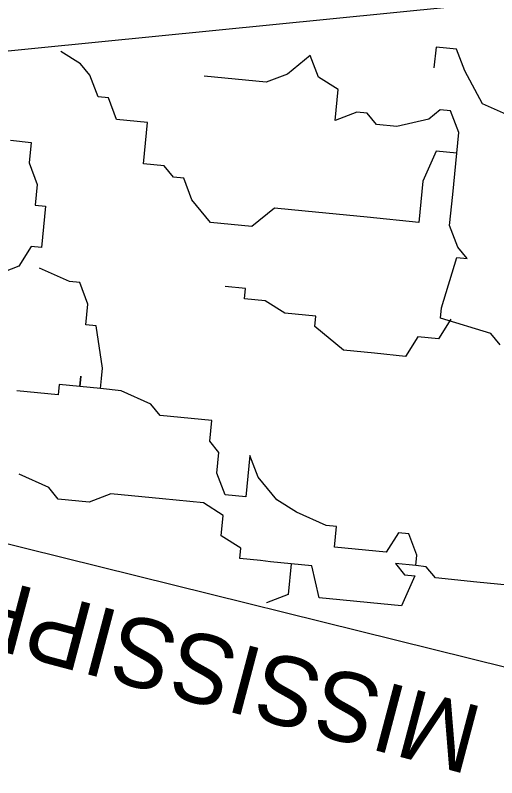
# Model space of a CAD drawing. Extents: x 1796928 to 1798191, y 245238 to 247038.
# Drawn here: x 1798053.46 to 1798065.67, y 246154.02 to 246173.35 of the extents above; entities that cross this region are included whole.
import ezdxf

# ---------------------------------------------------------------- set-up
doc = ezdxf.new("R2010")
doc.units = 0
doc.layers.add('great seal', color=7, linetype='Continuous')

msp = doc.modelspace()

# ---------------------------------------------------------------- linework, layer by layer
at = {"layer": 'great seal'}
msp.add_line((1798064.506, 246165.645), (1798064.506, 246165.645), dxfattribs=at)
msp.add_line((1798064.506, 246165.645), (1798064.506, 246165.645), dxfattribs=at)
msp.add_line((1798064.506, 246165.645), (1798064.506, 246165.645), dxfattribs=at)
msp.add_line((1798064.506, 246165.645), (1798064.506, 246165.645), dxfattribs=at)
msp.add_line((1798064.506, 246165.645), (1798064.506, 246165.645), dxfattribs=at)
msp.add_line((1798064.506, 246165.645), (1798064.506, 246165.645), dxfattribs=at)
for points in [[(1798052.498, 246172.378), (1798064.498, 246173.567)], [(1798052.498, 246172.378), (1798064.498, 246173.567)], [(1798052.498, 246172.378), (1798064.498, 246173.567)], [(1798071.46, 246166.541), (1798071.46, 246166.541), (1798070.676, 246166.619), (1798070.44, 246166.906), (1798070.179, 246166.932), (1798069.656, 246166.984), (1798069.682, 246167.245), (1798069.185, 246167.559), (1798069.001, 246168.369), (1798068.504, 246168.682), (1798068.581, 246169.467), (1798068.058, 246169.518), (1798067.064, 246170.145), (1798066.541, 246170.197), (1798066.541, 246170.197), (1798066.28, 246170.222), (1798066.305, 246170.484), (1798066.07, 246170.771), (1798065.311, 246171.11), (1798064.866, 246171.947), (1798064.656, 246172.495), (1798064.395, 246172.521), (1798064.133, 246172.547), (1798064.081, 246172.024)], [(1798071.46, 246166.541), (1798071.46, 246166.541), (1798070.676, 246166.619), (1798070.44, 246166.906), (1798070.179, 246166.932), (1798069.656, 246166.984), (1798069.682, 246167.245), (1798069.185, 246167.559), (1798069.001, 246168.369), (1798068.504, 246168.682), (1798068.581, 246169.467), (1798068.058, 246169.518), (1798067.064, 246170.145), (1798066.541, 246170.197), (1798066.541, 246170.197), (1798066.28, 246170.222), (1798066.305, 246170.484), (1798066.07, 246170.771), (1798065.311, 246171.11), (1798064.866, 246171.947), (1798064.656, 246172.495), (1798064.395, 246172.521), (1798064.133, 246172.547), (1798064.081, 246172.024)], [(1798071.46, 246166.541), (1798071.46, 246166.541), (1798070.676, 246166.619), (1798070.44, 246166.906), (1798070.179, 246166.932), (1798069.656, 246166.984), (1798069.682, 246167.245), (1798069.185, 246167.559), (1798069.001, 246168.369), (1798068.504, 246168.682), (1798068.581, 246169.467), (1798068.058, 246169.518), (1798067.064, 246170.145), (1798066.541, 246170.197), (1798066.541, 246170.197), (1798066.28, 246170.222), (1798066.305, 246170.484), (1798066.07, 246170.771), (1798065.311, 246171.11), (1798064.866, 246171.947), (1798064.656, 246172.495), (1798064.395, 246172.521), (1798064.133, 246172.547), (1798064.081, 246172.024)], [(1798064.659, 246169.855), (1798064.136, 246169.906), (1798063.797, 246169.148), (1798063.771, 246168.886), (1798063.693, 246168.102), (1798062.386, 246168.231), (1798062.386, 246168.231), (1798062.124, 246168.257), (1798061.34, 246168.335), (1798060.817, 246168.386), (1798060.033, 246168.464), (1798059.458, 246167.993), (1798058.412, 246168.096), (1798057.941, 246168.671), (1798057.731, 246169.22), (1798057.469, 246169.246), (1798057.234, 246169.533), (1798056.711, 246169.585), (1798056.814, 246170.631), (1798056.291, 246170.683), (1798056.03, 246170.708), (1798055.82, 246171.257), (1798055.559, 246171.283), (1798055.349, 246171.832), (1798055.113, 246172.119), (1798054.616, 246172.433)], [(1798064.659, 246169.855), (1798064.136, 246169.906), (1798063.797, 246169.148), (1798063.771, 246168.886), (1798063.693, 246168.102), (1798062.386, 246168.231), (1798062.386, 246168.231), (1798062.124, 246168.257), (1798061.34, 246168.335), (1798060.817, 246168.386), (1798060.033, 246168.464), (1798059.458, 246167.993), (1798058.412, 246168.096), (1798057.941, 246168.671), (1798057.731, 246169.22), (1798057.469, 246169.246), (1798057.234, 246169.533), (1798056.711, 246169.585), (1798056.814, 246170.631), (1798056.291, 246170.683), (1798056.03, 246170.708), (1798055.82, 246171.257), (1798055.559, 246171.283), (1798055.349, 246171.832), (1798055.113, 246172.119), (1798054.616, 246172.433)], [(1798064.659, 246169.855), (1798064.136, 246169.906), (1798063.797, 246169.148), (1798063.771, 246168.886), (1798063.693, 246168.102), (1798062.386, 246168.231), (1798062.386, 246168.231), (1798062.124, 246168.257), (1798061.34, 246168.335), (1798060.817, 246168.386), (1798060.033, 246168.464), (1798059.458, 246167.993), (1798058.412, 246168.096), (1798057.941, 246168.671), (1798057.731, 246169.22), (1798057.469, 246169.246), (1798057.234, 246169.533), (1798056.711, 246169.585), (1798056.814, 246170.631), (1798056.291, 246170.683), (1798056.03, 246170.708), (1798055.82, 246171.257), (1798055.559, 246171.283), (1798055.349, 246171.832), (1798055.113, 246172.119), (1798054.616, 246172.433)], [(1798065.762, 246164.993), (1798065.526, 246165.28), (1798064.245, 246165.671), (1798064.271, 246165.932), (1798064.662, 246167.214), (1798064.923, 246167.188), (1798064.688, 246167.475), (1798064.478, 246168.024), (1798064.555, 246168.809), (1798064.659, 246169.855), (1798064.711, 246170.378), (1798064.501, 246170.926), (1798064.239, 246170.952), (1798063.952, 246170.717), (1798063.952, 246170.717), (1798063.142, 246170.533), (1798062.619, 246170.585), (1798062.383, 246170.872), (1798062.122, 246170.898), (1798061.573, 246170.688), (1798061.65, 246171.473), (1798061.153, 246171.786), (1798060.944, 246172.335), (1798060.369, 246171.863), (1798060.369, 246171.863), (1798059.82, 246171.654), (1798059.297, 246171.705), (1798058.251, 246171.809)], [(1798065.762, 246164.993), (1798065.526, 246165.28), (1798064.245, 246165.671), (1798064.271, 246165.932), (1798064.662, 246167.214), (1798064.923, 246167.188), (1798064.688, 246167.475), (1798064.478, 246168.024), (1798064.555, 246168.809), (1798064.659, 246169.855), (1798064.711, 246170.378), (1798064.501, 246170.926), (1798064.239, 246170.952), (1798063.952, 246170.717), (1798063.952, 246170.717), (1798063.142, 246170.533), (1798062.619, 246170.585), (1798062.383, 246170.872), (1798062.122, 246170.898), (1798061.573, 246170.688), (1798061.65, 246171.473), (1798061.153, 246171.786), (1798060.944, 246172.335), (1798060.369, 246171.863), (1798060.369, 246171.863), (1798059.82, 246171.654), (1798059.297, 246171.705), (1798058.251, 246171.809)], [(1798065.762, 246164.993), (1798065.526, 246165.28), (1798064.245, 246165.671), (1798064.271, 246165.932), (1798064.662, 246167.214), (1798064.923, 246167.188), (1798064.688, 246167.475), (1798064.478, 246168.024), (1798064.555, 246168.809), (1798064.659, 246169.855), (1798064.711, 246170.378), (1798064.501, 246170.926), (1798064.239, 246170.952), (1798063.952, 246170.717), (1798063.952, 246170.717), (1798063.142, 246170.533), (1798062.619, 246170.585), (1798062.383, 246170.872), (1798062.122, 246170.898), (1798061.573, 246170.688), (1798061.65, 246171.473), (1798061.153, 246171.786), (1798060.944, 246172.335), (1798060.369, 246171.863), (1798060.369, 246171.863), (1798059.82, 246171.654), (1798059.297, 246171.705), (1798058.251, 246171.809)], [(1798053.337, 246170.183), (1798053.86, 246170.131), (1798053.809, 246169.608), (1798054.018, 246169.059), (1798053.992, 246168.798), (1798053.967, 246168.536), (1798054.228, 246168.51), (1798054.202, 246168.249), (1798054.202, 246168.249), (1798054.125, 246167.464), (1798054.125, 246167.464), (1798053.863, 246167.49), (1798053.55, 246166.993), (1798053.001, 246166.783)], [(1798053.337, 246170.183), (1798053.86, 246170.131), (1798053.809, 246169.608), (1798054.018, 246169.059), (1798053.992, 246168.798), (1798053.967, 246168.536), (1798054.228, 246168.51), (1798054.202, 246168.249), (1798054.202, 246168.249), (1798054.125, 246167.464), (1798054.125, 246167.464), (1798053.863, 246167.49), (1798053.55, 246166.993), (1798053.001, 246166.783)], [(1798053.337, 246170.183), (1798053.86, 246170.131), (1798053.809, 246169.608), (1798054.018, 246169.059), (1798053.992, 246168.798), (1798053.967, 246168.536), (1798054.228, 246168.51), (1798054.202, 246168.249), (1798054.202, 246168.249), (1798054.125, 246167.464), (1798054.125, 246167.464), (1798053.863, 246167.49), (1798053.55, 246166.993), (1798053.001, 246166.783)], [(1798063.624, 246159.395), (1798063.624, 246159.395), (1798063.65, 246159.657), (1798063.65, 246159.657), (1798063.44, 246160.206), (1798063.179, 246160.231), (1798062.865, 246159.734), (1798062.865, 246159.734), (1798062.081, 246159.812), (1798061.558, 246159.864), (1798061.61, 246160.387), (1798061.348, 246160.412), (1798060.59, 246160.752), (1798060.093, 246161.065), (1798059.621, 246161.64), (1798059.412, 246162.188), (1798059.36, 246161.665), (1798059.308, 246161.142), (1798058.785, 246161.194), (1798058.575, 246161.743), (1798058.575, 246161.743), (1798058.627, 246162.266), (1798058.391, 246162.553), (1798058.391, 246162.553), (1798058.443, 246163.076), (1798057.92, 246163.128), (1798057.397, 246163.18), (1798057.397, 246163.18), (1798057.136, 246163.206), (1798056.9, 246163.493), (1798056.142, 246163.832), (1798056.142, 246163.832), (1798055.619, 246163.884), (1798055.644, 246164.145), (1798055.67, 246164.407), (1798055.67, 246164.407), (1798055.512, 246165.479), (1798055.251, 246165.505), (1798055.303, 246166.028), (1798055.093, 246166.576), (1798054.831, 246166.602), (1798054.073, 246166.941)], [(1798063.624, 246159.395), (1798063.624, 246159.395), (1798063.65, 246159.657), (1798063.65, 246159.657), (1798063.44, 246160.206), (1798063.179, 246160.231), (1798062.865, 246159.734), (1798062.865, 246159.734), (1798062.081, 246159.812), (1798061.558, 246159.864), (1798061.61, 246160.387), (1798061.348, 246160.412), (1798060.59, 246160.752), (1798060.093, 246161.065), (1798059.621, 246161.64), (1798059.412, 246162.188), (1798059.36, 246161.665), (1798059.308, 246161.142), (1798058.785, 246161.194), (1798058.575, 246161.743), (1798058.575, 246161.743), (1798058.627, 246162.266), (1798058.391, 246162.553), (1798058.391, 246162.553), (1798058.443, 246163.076), (1798057.92, 246163.128), (1798057.397, 246163.18), (1798057.397, 246163.18), (1798057.136, 246163.206), (1798056.9, 246163.493), (1798056.142, 246163.832), (1798056.142, 246163.832), (1798055.619, 246163.884), (1798055.644, 246164.145), (1798055.67, 246164.407), (1798055.67, 246164.407), (1798055.512, 246165.479), (1798055.251, 246165.505), (1798055.303, 246166.028), (1798055.093, 246166.576), (1798054.831, 246166.602), (1798054.073, 246166.941)], [(1798063.624, 246159.395), (1798063.624, 246159.395), (1798063.65, 246159.657), (1798063.65, 246159.657), (1798063.44, 246160.206), (1798063.179, 246160.231), (1798062.865, 246159.734), (1798062.865, 246159.734), (1798062.081, 246159.812), (1798061.558, 246159.864), (1798061.61, 246160.387), (1798061.348, 246160.412), (1798060.59, 246160.752), (1798060.093, 246161.065), (1798059.621, 246161.64), (1798059.412, 246162.188), (1798059.36, 246161.665), (1798059.308, 246161.142), (1798058.785, 246161.194), (1798058.575, 246161.743), (1798058.575, 246161.743), (1798058.627, 246162.266), (1798058.391, 246162.553), (1798058.391, 246162.553), (1798058.443, 246163.076), (1798057.92, 246163.128), (1798057.397, 246163.18), (1798057.397, 246163.18), (1798057.136, 246163.206), (1798056.9, 246163.493), (1798056.142, 246163.832), (1798056.142, 246163.832), (1798055.619, 246163.884), (1798055.644, 246164.145), (1798055.67, 246164.407), (1798055.67, 246164.407), (1798055.512, 246165.479), (1798055.251, 246165.505), (1798055.303, 246166.028), (1798055.093, 246166.576), (1798054.831, 246166.602), (1798054.073, 246166.941)], [(1798064.506, 246165.645), (1798064.193, 246165.148), (1798063.932, 246165.174), (1798063.67, 246165.2), (1798063.357, 246164.703), (1798062.573, 246164.78), (1798062.05, 246164.832), (1798061.788, 246164.858), (1798061.788, 246164.858), (1798061.055, 246165.458), (1798061.081, 246165.72), (1798060.297, 246165.797), (1798059.8, 246166.111), (1798059.8, 246166.111), (1798059.277, 246166.162), (1798059.303, 246166.424), (1798058.78, 246166.476)], [(1798064.506, 246165.645), (1798064.193, 246165.148), (1798063.932, 246165.174), (1798063.67, 246165.2), (1798063.357, 246164.703), (1798062.573, 246164.78), (1798062.05, 246164.832), (1798061.788, 246164.858), (1798061.788, 246164.858), (1798061.055, 246165.458), (1798061.081, 246165.72), (1798060.297, 246165.797), (1798059.8, 246166.111), (1798059.8, 246166.111), (1798059.277, 246166.162), (1798059.303, 246166.424), (1798058.78, 246166.476)], [(1798064.506, 246165.645), (1798064.193, 246165.148), (1798063.932, 246165.174), (1798063.67, 246165.2), (1798063.357, 246164.703), (1798062.573, 246164.78), (1798062.05, 246164.832), (1798061.788, 246164.858), (1798061.788, 246164.858), (1798061.055, 246165.458), (1798061.081, 246165.72), (1798060.297, 246165.797), (1798059.8, 246166.111), (1798059.8, 246166.111), (1798059.277, 246166.162), (1798059.303, 246166.424), (1798058.78, 246166.476)], [(1798055.619, 246163.884), (1798055.357, 246163.91), (1798055.096, 246163.936), (1798055.122, 246164.197), (1798055.096, 246163.936), (1798054.834, 246163.962), (1798054.573, 246163.987), (1798054.547, 246163.726), (1798054.285, 246163.752), (1798053.762, 246163.804), (1798053.501, 246163.829)], [(1798055.619, 246163.884), (1798055.357, 246163.91), (1798055.096, 246163.936), (1798055.122, 246164.197), (1798055.096, 246163.936), (1798054.834, 246163.962), (1798054.573, 246163.987), (1798054.547, 246163.726), (1798054.285, 246163.752), (1798053.762, 246163.804), (1798053.501, 246163.829)], [(1798055.619, 246163.884), (1798055.357, 246163.91), (1798055.096, 246163.936), (1798055.122, 246164.197), (1798055.096, 246163.936), (1798054.834, 246163.962), (1798054.573, 246163.987), (1798054.547, 246163.726), (1798054.285, 246163.752), (1798053.762, 246163.804), (1798053.501, 246163.829)], [(1798060.46, 246159.444), (1798059.937, 246159.496), (1798059.676, 246159.522), (1798059.153, 246159.574), (1798059.179, 246159.835), (1798058.682, 246160.148), (1798058.733, 246160.671), (1798058.236, 246160.984), (1798057.19, 246161.088), (1798056.667, 246161.14), (1798056.406, 246161.166), (1798055.883, 246161.217), (1798055.334, 246161.008), (1798054.811, 246161.059), (1798054.55, 246161.085), (1798054.314, 246161.373), (1798053.555, 246161.712)], [(1798060.46, 246159.444), (1798059.937, 246159.496), (1798059.676, 246159.522), (1798059.153, 246159.574), (1798059.179, 246159.835), (1798058.682, 246160.148), (1798058.733, 246160.671), (1798058.236, 246160.984), (1798057.19, 246161.088), (1798056.667, 246161.14), (1798056.406, 246161.166), (1798055.883, 246161.217), (1798055.334, 246161.008), (1798054.811, 246161.059), (1798054.55, 246161.085), (1798054.314, 246161.373), (1798053.555, 246161.712)], [(1798060.46, 246159.444), (1798059.937, 246159.496), (1798059.676, 246159.522), (1798059.153, 246159.574), (1798059.179, 246159.835), (1798058.682, 246160.148), (1798058.733, 246160.671), (1798058.236, 246160.984), (1798057.19, 246161.088), (1798056.667, 246161.14), (1798056.406, 246161.166), (1798055.883, 246161.217), (1798055.334, 246161.008), (1798054.811, 246161.059), (1798054.55, 246161.085), (1798054.314, 246161.373), (1798053.555, 246161.712)], [(1798076.963, 246155.435), (1798067.811, 246156.34), (1798051.831, 246160.298)], [(1798076.963, 246155.435), (1798067.811, 246156.34), (1798051.831, 246160.298)], [(1798076.963, 246155.435), (1798067.811, 246156.34), (1798051.831, 246160.298)], [(1798065.951, 246158.901), (1798065.429, 246158.953), (1798065.429, 246158.953), (1798065.167, 246158.978), (1798064.121, 246159.082), (1798064.121, 246159.082), (1798063.885, 246159.369), (1798063.624, 246159.395), (1798063.101, 246159.447), (1798063.337, 246159.16), (1798063.598, 246159.134), (1798063.259, 246158.375), (1798062.998, 246158.401), (1798062.736, 246158.427), (1798062.736, 246158.427), (1798061.429, 246158.556), (1798061.429, 246158.556), (1798061.167, 246158.582), (1798060.983, 246159.392), (1798060.46, 246159.444), (1798060.383, 246158.66), (1798059.834, 246158.45), (1798059.834, 246158.45)], [(1798065.951, 246158.901), (1798065.429, 246158.953), (1798065.429, 246158.953), (1798065.167, 246158.978), (1798064.121, 246159.082), (1798064.121, 246159.082), (1798063.885, 246159.369), (1798063.624, 246159.395), (1798063.101, 246159.447), (1798063.337, 246159.16), (1798063.598, 246159.134), (1798063.259, 246158.375), (1798062.998, 246158.401), (1798062.736, 246158.427), (1798062.736, 246158.427), (1798061.429, 246158.556), (1798061.429, 246158.556), (1798061.167, 246158.582), (1798060.983, 246159.392), (1798060.46, 246159.444), (1798060.383, 246158.66), (1798059.834, 246158.45), (1798059.834, 246158.45)], [(1798065.951, 246158.901), (1798065.429, 246158.953), (1798065.429, 246158.953), (1798065.167, 246158.978), (1798064.121, 246159.082), (1798064.121, 246159.082), (1798063.885, 246159.369), (1798063.624, 246159.395), (1798063.101, 246159.447), (1798063.337, 246159.16), (1798063.598, 246159.134), (1798063.259, 246158.375), (1798062.998, 246158.401), (1798062.736, 246158.427), (1798062.736, 246158.427), (1798061.429, 246158.556), (1798061.429, 246158.556), (1798061.167, 246158.582), (1798060.983, 246159.392), (1798060.46, 246159.444), (1798060.383, 246158.66), (1798059.834, 246158.45), (1798059.834, 246158.45)]]:
    msp.add_lwpolyline(points, dxfattribs=at)
for radius in [22.994, 22.994, 22.994, 22.389, 22.389, 22.389, 17.779, 17.779, 17.779, 17.222, 17.222, 17.222]:
    msp.add_circle((1798064.692, 246165.645), radius, dxfattribs=at)

# ---------------------------------------------------------------- texts
msp.add_text('MISSISSIPPI', height=1.75474, rotation=165.2023, dxfattribs=at).set_placement((1798065.38, 246155.789))
msp.add_text('MISSISSIPPI', height=1.75474, rotation=165.2023, dxfattribs=at).set_placement((1798065.38, 246155.789))
msp.add_text('MISSISSIPPI', height=1.75474, rotation=165.2023, dxfattribs=at).set_placement((1798065.38, 246155.789))

doc.saveas('drawing.dxf')
